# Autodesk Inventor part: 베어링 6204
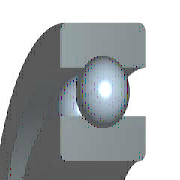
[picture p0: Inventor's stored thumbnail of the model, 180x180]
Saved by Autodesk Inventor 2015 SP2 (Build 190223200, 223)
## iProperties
IsCustomPart: 0
Created: 2015-12
Part Number: 베어링 6204
Material: 강철, 연강
Description: 깊은 그루브 볼 베어링
Document SubType Name: Modeling
Standard: KS B 2023
Designer: mdu
Standards Organization: KS
Language: ko-KR
Size Designation: 6204 - 20 x 47 x 14
Categories: <MemberInstance><Categories><Category DisplayName="샤프트 부품" InternalName="7f7aeb1f-a693-4053-b835-cee3144e0d98" Mnemonic="SHFT"><Category DisplayName="베어링" Inter
Density: 7.86 g/cm^3
Mass: 104.255 g
Surface Area: 87.8912 cm^2
Volume: 13.264 cm^3
Appearance: 강철
Author: mud
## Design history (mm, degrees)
sketch "스케치" dims "d0" = 7.02 (= -0.26 x WD + 0.26 x BD)
  geometry: L1 (3.49, 16.75)-(10.51, 16.75); L2 (7, 16.75)-(7, 13.24); L3 (7, 16.75)-(7, 20.26); L4 (4.392, 14.401)-(0, 14.401); L5 (0, 10)-(14, 10); L6 (4.392, 19.099)-(0, 19.099); L7 (0, 23.5)-(14, 23.5); L8 (14, 10)-(14, 14.401); L9 (9.608, 14.401)-(14, 14.401); L10 (9.608, 19.099)-(14, 19.099); L11 (14, 23.5)-(14, 19.099); L12 (-1.4, 0)-(8.4, 0) reference; L13 (0, -0.3)-(0, 5.3) reference
  constraints: 22 end point, 4 point on line, 2 collinear, 2 perpendicular, 2 symmetric about line, 1 midpoint, 1 parallel, 14 other
  dimensions: "d9" = 20 diameter of L5 L12 (= WD); "d11" = 47 diameter of L7 L12 (= BD); "d12" = 14 distance between parallel lines of L8 L13 (= KB); "d13" = 28.802 diameter of L9 L12 (= 0.326 x BD + 0.674 x WD)
revolve "본체" stored, may be unused: angle "d6" = 90 deg
revolve "볼" stored, may be unused: angle "d7" = 90 deg
pattern_circular "IDS_ARRAYBALL[SIMPL:T]" dims angle "d3" = 360 deg
body "Solid1"
fillet "모깎기1" dims "d1" = 1 (= KRS)
other parameters: "WD" = 20 [user parameter; used in 5 equation terms], "BD" = 47 [user parameter; used in 5 equation terms], "KB" = 14 [user parameter; used in 1 equation term], "KRS" = 1 [user parameter; used in 1 equation term], "d4" = 0, "d5" = 0, "d8" = 0, "d14" = 0, "d15" = 0, "BBA" = 0 [user parameter], "BC0" = 6550000 [user parameter], "BC" = 1.27e+07 [user parameter], "BR" = 23.5 (= 0.5 x BD) [user parameter]
